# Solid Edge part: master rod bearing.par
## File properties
Author: Deepak Maini
Template: Normal.par
Last saved by: Robert a Rhodes jr
Revision: 2
Application: Solid Edge
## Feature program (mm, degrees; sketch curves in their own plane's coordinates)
sketch for "unnamed Protrusion 1" #1 plane through (0, 0, 0) normal (0, 0, 1) x-axis (1, 0, 0)
  circle centre (0, 0) radius 23
sketch for "unnamed Protrusion 1" #2 plane through (0, 0, 0) normal (0, 0, 1) x-axis (1, 0, 0)
  circle centre (0, 0) radius 26
extrude "unnamed Protrusion 1" add finite 70 along -normal
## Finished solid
Body 1: solid body, 4 faces, 4 edges, 0 vertices.
  Faces by surface: cylinder 2, plane 2
  Edges by curve: circle 4
Bounding box of the edges (mm): 52.000 x 52.000 x 70.000, from (-26, -26, -70) to (26, 26, 0).
Cylindrical faces by radius (mm): R23 x1, R26 x1
Planar faces by outward normal: +z 1, -z 1
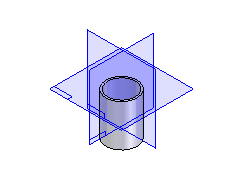
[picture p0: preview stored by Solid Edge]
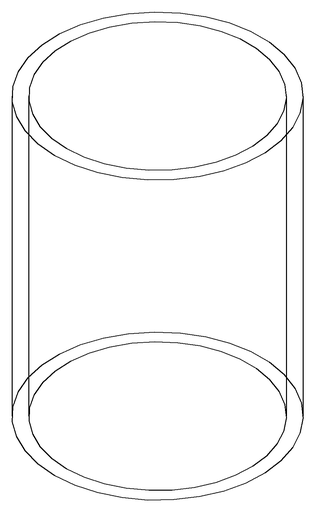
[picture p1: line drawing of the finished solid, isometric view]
